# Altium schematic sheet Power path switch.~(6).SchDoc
size A3; SheetNumber: 6; SheetTotal: 6
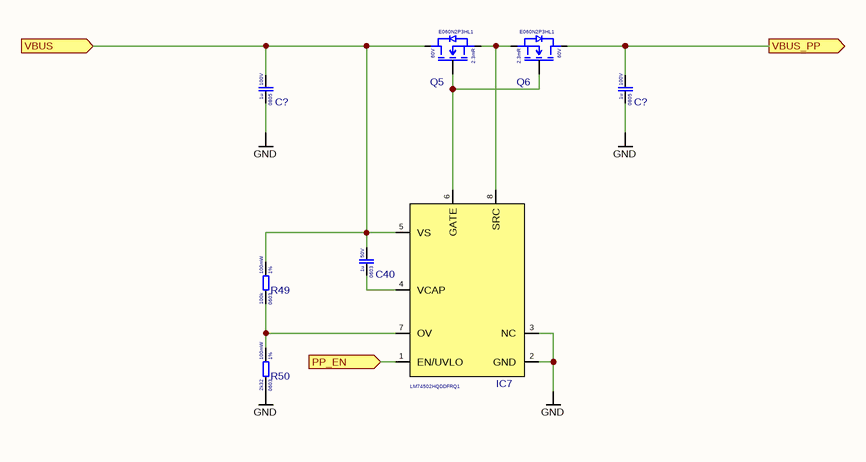
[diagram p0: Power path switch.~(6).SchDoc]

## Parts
(Parts that share a designator on the sheet are numbered #1, #2 ... from top to bottom, then left to right.)
C40  Voltage Rating: 50V  Case Code (Imperial): 0603  Capacitance: 1u  [CAP 0603]  (hidden comment: CL10A105KB8NNNC)
C?#1  Voltage Rating: 100V  Case Code (Imperial): 0805  Capacitance: 1u  [Cap_0805]  (hidden comment: CC0805KKX7R0BB105)
C?#2  Voltage Rating: 100V  Case Code (Imperial): 0805  Capacitance: 1u  [Cap_0805]  (hidden comment: CC0805KKX7R0BB105)
IC7  LM74502HQDDFRQ1  [SOT-23-8]
Q5  Rds: 2.3mR  Voltage: 60V  [DFN-8 (5x6)]  (hidden comment: E060N2P3HL1)
Q6  Rds: 2.3mR  Voltage: 60V  [DFN-8 (5x6)]  (hidden comment: E060N2P3HL1)
R49  Resistance Tolerance: 1%  Resistance: 100k  Power Rating: 100mW  Case Code (Imperial): 0603  [RES_0603]  (hidden comment: 0603WAF1003T5E)
R50  Resistance Tolerance: 1%  Resistance: 2k32  Power Rating: 100mW  Case Code (Imperial): 0603  [RES_0603]  (hidden comment: FRC0603F2321TS)

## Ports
PP_EN (in, see Arhitecture[4A], USB PD[6A]), VBUS (in, see Arhitecture[3A]), VBUS_PP (out, see Arhitecture[4A])

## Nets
GND: C?#1.1 C?#2.1 IC7.2(GND) IC7.3(NC) R50.1
PP_EN: IC7.1(EN/UVLO) ; port PP_EN
VBUS: C40.2 C?#1.2 IC7.5(VS) Q5.D R49.2 ; port VBUS
VBUS_PP: C?#2.2 Q6.D ; port VBUS_PP
NetC40_1: C40.1 IC7.4(VCAP)
NetIC7_6: IC7.6(GATE) Q5.G Q6.G
NetIC7_7: IC7.7(OV) R49.1 R50.2
NetIC7_8: IC7.8(SRC) Q5.S Q6.S

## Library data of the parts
C40 = CL10A105KB8NNNC: Cap 1uF 50V 0603 X5R; Manufacturer: Samsung
C?#1 C?#2 = CC0805KKX7R0BB105: Cap 1uF 100V 0805 X7R; Manufacturer: Yageo
IC7 = LM74502HQDDFRQ1: High-side switch controller IC 3.2~65V Reverse polarity protection; Manufacturer: Texas Instruments
Q5 Q6 = E060N2P3HL1: Nmos 60V 180A 2.3mR PDFN5x6-8; Manufacturer: Existar
R49 = 0603WAF1003T5E: Res 100k 0603 1% 100mW 75V; Manufacturer: Uni-Royal
R50 = FRC0603F2321TS: Res 2k32 0603 1% 100mW 75V; Manufacturer: Uni-Royal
